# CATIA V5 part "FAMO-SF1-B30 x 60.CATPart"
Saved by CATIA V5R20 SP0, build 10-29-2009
Part number: FAMO-SF1-B30 x 60
Definition: NONE
Nomenclature: FAMO-SF1-B30 x 60
Source: Unknown
Description: FAMO-SF1-B30 x 60
Bounding box of the stored display mesh (mm): x -13 to 47, y -26.5 to 26.5, z -26.5 to 26.5
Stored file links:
  C:\Users\Utente\Desktop\IO LAVORO\3D X SITO CF\X SITO\FAMO\FAMO-SF1-B30 x 60.CATPart
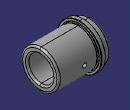
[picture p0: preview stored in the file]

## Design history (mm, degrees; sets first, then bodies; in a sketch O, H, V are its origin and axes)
Body1 "FAMO-SF1-B30 x 60" (main body)
  Solid1: solid without history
